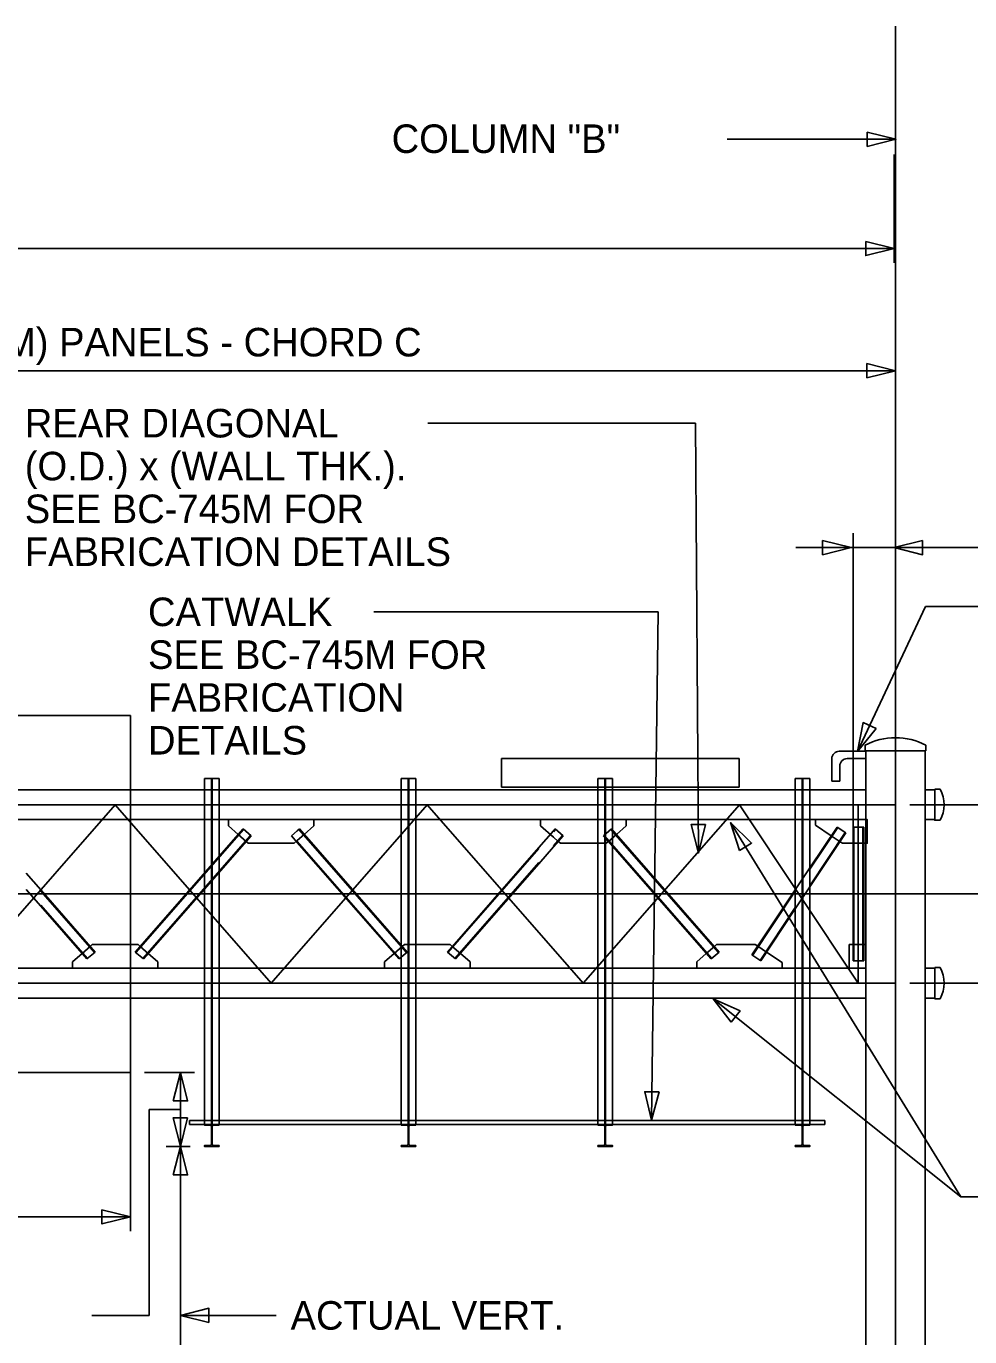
# Model space of a CAD drawing. Extents: x 3831399 to 3833095, y 499014 to 500202.
# Drawn here: x 3832657.9 to 3832754.1, y 499854.4 to 499988 of the extents above; entities that cross this region are included whole.
import ezdxf

# ---------------------------------------------------------------- set-up
doc = ezdxf.new("R2010")
doc.units = 0
for name, color, linetype in [('0-catwalk', 7, 'Continuous'), ('0-sign', 7, 'Continuous'), ('0-truss', 7, 'Continuous'), ('CenterLine', 7, 'Continuous'), ('Default', 7, 'Continuous'), ('DIM TXT', 7, 'Continuous'), ('structure', 7, 'Continuous')]:
    doc.layers.add(name, color=color, linetype=linetype)

msp = doc.modelspace()

# ---------------------------------------------------------------- linework, layer by layer
at = {"layer": '0-catwalk'}
for p, q in [((3832676.03, 499911.3), (3832677.52, 499911.3)), ((3832676.03, 499876.06), (3832676.03, 499911.3)), ((3832676.74, 499911.3), (3832676.81, 499911.3)), ((3832676.74, 499876.06), (3832676.74, 499911.3)), ((3832676.81, 499911.3), (3832676.81, 499876.06)), ((3832677.52, 499911.3), (3832677.52, 499876.06)), ((3832696.09, 499911.3), (3832697.58, 499911.3)), ((3832696.09, 499876.06), (3832696.09, 499911.3)), ((3832696.8, 499911.3), (3832696.87, 499911.3)), ((3832696.8, 499876.06), (3832696.8, 499911.3)), ((3832696.87, 499911.3), (3832696.87, 499876.06)), ((3832697.58, 499911.3), (3832697.58, 499876.06)), ((3832716.15, 499911.3), (3832717.64, 499911.3)), ((3832716.15, 499876.06), (3832716.15, 499911.3)), ((3832716.86, 499911.3), (3832716.93, 499911.3)), ((3832716.86, 499876.06), (3832716.86, 499911.3)), ((3832716.93, 499911.3), (3832716.93, 499876.06)), ((3832717.64, 499911.3), (3832717.64, 499876.06)), ((3832736.27, 499911.3), (3832737.76, 499911.3)), ((3832736.27, 499876.06), (3832736.27, 499911.3)), ((3832736.99, 499911.3), (3832737.05, 499911.3)), ((3832736.99, 499876.06), (3832736.99, 499911.3)), ((3832737.05, 499911.3), (3832737.05, 499876.06)), ((3832737.76, 499911.3), (3832737.76, 499876.06)), ((3832739.29, 499876.44), (3832674.5, 499876.44)), ((3832674.5, 499876.44), (3832674.5, 499876.06)), ((3832739.29, 499876.06), (3832739.29, 499876.44)), ((3832674.5, 499876.06), (3832739.29, 499876.06)), ((3832677.52, 499876.06), (3832676.03, 499876.06)), ((3832676.81, 499876.06), (3832676.74, 499876.06)), ((3832697.58, 499876.06), (3832696.09, 499876.06)), ((3832696.87, 499876.06), (3832696.8, 499876.06)), ((3832717.64, 499876.06), (3832716.15, 499876.06)), ((3832716.93, 499876.06), (3832716.86, 499876.06)), ((3832737.76, 499876.06), (3832736.27, 499876.06)), ((3832737.05, 499876.06), (3832736.99, 499876.06))]:
    msp.add_line(p, q, dxfattribs=at)
for points in [[(3832676.03, 499876.06), (3832677.52, 499876.06), (3832677.52, 499875.98), (3832676.94, 499875.98)], [(3832676.61, 499875.98), (3832676.03, 499875.98), (3832676.03, 499876.06)], [(3832676.74, 499874.04), (3832676.74, 499875.85)], [(3832676.81, 499875.85), (3832676.81, 499874.04)], [(3832696.09, 499876.06), (3832697.58, 499876.06), (3832697.58, 499875.98), (3832697, 499875.98)], [(3832696.67, 499875.98), (3832696.09, 499875.98), (3832696.09, 499876.06)], [(3832696.8, 499874.04), (3832696.8, 499875.85)], [(3832696.87, 499875.85), (3832696.87, 499874.04)], [(3832716.15, 499876.06), (3832717.64, 499876.06), (3832717.64, 499875.98), (3832717.06, 499875.98)], [(3832716.73, 499875.98), (3832716.15, 499875.98), (3832716.15, 499876.06)], [(3832716.86, 499874.04), (3832716.86, 499875.85)], [(3832716.93, 499875.85), (3832716.93, 499874.04)], [(3832736.27, 499876.06), (3832737.76, 499876.06), (3832737.76, 499875.98), (3832737.18, 499875.98)], [(3832736.85, 499875.98), (3832736.27, 499875.98), (3832736.27, 499876.06)], [(3832736.99, 499874.04), (3832736.99, 499875.85)], [(3832737.05, 499875.85), (3832737.05, 499874.04)], [(3832676.94, 499873.9), (3832677.52, 499873.9), (3832677.52, 499873.82), (3832676.03, 499873.82), (3832676.03, 499873.9), (3832676.61, 499873.9)], [(3832697, 499873.9), (3832697.58, 499873.9), (3832697.58, 499873.82), (3832696.09, 499873.82), (3832696.09, 499873.9), (3832696.67, 499873.9)], [(3832717.06, 499873.9), (3832717.64, 499873.9), (3832717.64, 499873.82), (3832716.15, 499873.82), (3832716.15, 499873.9), (3832716.73, 499873.9)], [(3832737.18, 499873.9), (3832737.76, 499873.9), (3832737.76, 499873.82), (3832736.27, 499873.82), (3832736.27, 499873.9), (3832736.85, 499873.9)]]:
    msp.add_lwpolyline(points, dxfattribs=at)
for centre, start, end in [((3832676.61, 499875.85), 360, 90), ((3832676.94, 499875.85), 90, 180), ((3832696.67, 499875.85), 360, 90), ((3832697, 499875.85), 90, 180), ((3832716.73, 499875.85), 360, 90), ((3832717.06, 499875.85), 90, 180), ((3832736.85, 499875.85), 360, 90), ((3832737.18, 499875.85), 90, 180), ((3832676.61, 499874.04), 270, 360), ((3832676.94, 499874.04), 180, 270), ((3832696.67, 499874.04), 270, 360), ((3832697, 499874.04), 180, 270), ((3832716.73, 499874.04), 270, 360), ((3832717.06, 499874.04), 180, 270), ((3832736.85, 499874.04), 270, 360), ((3832737.18, 499874.04), 180, 270)]:
    msp.add_arc(centre, 0.132, start, end, dxfattribs=at)
at = {"layer": '0-sign'}
for p, q in [((3832668.48, 499917.74), (3832554.81, 499917.74)), ((3832668.48, 499881.36), (3832668.48, 499917.74)), ((3832554.81, 499881.36), (3832668.48, 499881.36))]:
    msp.add_line(p, q, dxfattribs=at)
at = {"layer": '0-truss'}
for p, q in [((3832743.39, 499914.15), (3832743.39, 499914.72)), ((3832749.59, 499914.15), (3832743.39, 499914.15)), ((3832743.46, 499914.15), (3832743.46, 499801.79)), ((3832749.52, 499914.15), (3832749.52, 499801.79)), ((3832749.59, 499914.72), (3832749.59, 499914.15)), ((3832537.29, 499910.16), (3832685.48, 499910.16)), ((3832685.48, 499910.16), (3832711.62, 499910.16)), ((3832711.62, 499910.16), (3832737.76, 499910.16)), ((3832737.76, 499910.16), (3832743.46, 499910.16)), ((3832749.52, 499910.16), (3832750.49, 499910.16)), ((3832750.49, 499910.23), (3832751.05, 499910.23)), ((3832537.29, 499907.13), (3832685.48, 499907.13)), ((3832685.48, 499907.13), (3832710.13, 499907.13)), ((3832710.13, 499907.13), (3832711.62, 499907.13)), ((3832711.62, 499907.13), (3832710.31, 499907.13)), ((3832710.31, 499907.13), (3832710.31, 499906.48)), ((3832711.62, 499907.13), (3832737.76, 499907.13)), ((3832737.76, 499907.13), (3832743.46, 499907.13)), ((3832749.52, 499907.13), (3832750.49, 499907.13)), ((3832679.96, 499906.18), (3832668.98, 499893.63)), ((3832680.02, 499906.13), (3832669.04, 499893.58)), ((3832678.48, 499906.48), (3832679.46, 499905.62)), ((3832679.46, 499905.62), (3832680.28, 499904.9)), ((3832680.78, 499905.47), (3832679.96, 499906.18)), ((3832684.89, 499905.47), (3832685.48, 499905.98)), ((3832685.48, 499905.98), (3832685.71, 499906.18)), ((3832685.48, 499904.98), (3832686.21, 499905.62)), ((3832685.65, 499906.13), (3832696.63, 499893.58)), ((3832685.71, 499906.18), (3832696.69, 499893.63)), ((3832686.21, 499905.62), (3832687.19, 499906.48)), ((3832710.13, 499904.29), (3832711.62, 499905.99)), ((3832710.31, 499906.48), (3832711.62, 499905.33)), ((3832711.79, 499906.18), (3832711.62, 499905.99)), ((3832711.84, 499906.13), (3832711.62, 499905.88)), ((3832712.61, 499905.47), (3832711.79, 499906.18)), ((3832716.72, 499905.47), (3832717.54, 499906.18)), ((3832717.22, 499904.9), (3832718.04, 499905.62)), ((3832728.46, 499893.58), (3832717.48, 499906.13)), ((3832717.54, 499906.18), (3832728.52, 499893.63)), ((3832718.04, 499905.62), (3832719.02, 499906.48)), ((3832740.53, 499906.37), (3832737.76, 499902.22)), ((3832740.6, 499906.33), (3832737.76, 499902.08)), ((3832741.37, 499905.81), (3832737.76, 499900.39)), ((3832737.76, 499900.26), (3832741.44, 499905.77)), ((3832739.93, 499905.47), (3832738.32, 499906.55)), ((3832741.44, 499905.77), (3832740.53, 499906.37)), ((3832742.16, 499892.73), (3832742.16, 499906.37)), ((3832742.16, 499906.37), (3832743.25, 499906.37)), ((3832742.23, 499906.37), (3832742.23, 499892.73)), ((3832743.17, 499906.37), (3832743.17, 499892.73)), ((3832743.25, 499906.37), (3832743.25, 499892.73)), ((3832680.72, 499905.52), (3832669.74, 499892.97)), ((3832669.8, 499892.92), (3832680.78, 499905.47)), ((3832680.28, 499904.9), (3832680.5, 499904.71)), ((3832683.98, 499904.71), (3832685.17, 499904.71)), ((3832685.48, 499904.8), (3832684.89, 499905.47)), ((3832685.17, 499904.71), (3832685.48, 499904.98)), ((3832685.48, 499904.91), (3832695.93, 499892.97)), ((3832695.87, 499892.92), (3832685.48, 499904.8)), ((3832710.13, 499904.29), (3832700.81, 499893.63)), ((3832711.62, 499904.34), (3832710.13, 499902.63)), ((3832712.55, 499905.52), (3832711.62, 499904.46)), ((3832711.62, 499904.34), (3832712.61, 499905.47)), ((3832711.62, 499905.33), (3832712.11, 499904.9)), ((3832712.11, 499904.9), (3832712.32, 499904.71)), ((3832727.7, 499892.92), (3832716.72, 499905.47)), ((3832727.76, 499892.97), (3832716.78, 499905.52)), ((3832717, 499904.71), (3832717.22, 499904.9)), ((3832739.93, 499905.47), (3832740.84, 499904.87)), ((3832741.08, 499904.71), (3832740.84, 499904.87)), ((3832742.16, 499904.71), (3832743.25, 499904.71)), ((3832710.13, 499904.17), (3832700.86, 499893.58)), ((3832657.84, 499901.66), (3832659.33, 499899.96)), ((3832710.13, 499902.75), (3832701.57, 499892.97)), ((3832701.63, 499892.92), (3832710.13, 499902.63)), ((3832736.27, 499899.98), (3832737.76, 499902.22)), ((3832657.84, 499900.01), (3832659.33, 499898.3)), ((3832659.33, 499899.96), (3832664.87, 499893.63)), ((3832659.33, 499899.84), (3832664.81, 499893.58)), ((3832736.27, 499899.98), (3832731.84, 499893.33)), ((3832736.27, 499899.84), (3832731.9, 499893.29)), ((3832736.27, 499898.02), (3832737.76, 499900.26)), ((3832659.33, 499898.42), (3832664.1, 499892.97)), ((3832664.05, 499892.92), (3832659.33, 499898.3)), ((3832736.27, 499898.16), (3832732.68, 499892.77)), ((3832732.75, 499892.73), (3832736.27, 499898.02)), ((3832663.55, 499893.48), (3832664.37, 499894.2)), ((3832664.87, 499893.63), (3832664.05, 499892.92)), ((3832664.58, 499894.39), (3832664.37, 499894.2)), ((3832668.98, 499893.63), (3832669.8, 499892.92)), ((3832669.47, 499894.2), (3832669.26, 499894.39)), ((3832669.47, 499894.2), (3832670.29, 499893.48)), ((3832695.38, 499893.48), (3832696.2, 499894.2)), ((3832696.69, 499893.63), (3832695.87, 499892.92)), ((3832696.41, 499894.39), (3832696.2, 499894.2)), ((3832700.81, 499893.63), (3832701.63, 499892.92)), ((3832701.3, 499894.2), (3832701.09, 499894.39)), ((3832701.3, 499894.2), (3832702.12, 499893.48)), ((3832727.2, 499893.48), (3832728.02, 499894.2)), ((3832728.52, 499893.63), (3832727.7, 499892.92)), ((3832728.02, 499894.2), (3832728.24, 499894.39)), ((3832728.24, 499894.39), (3832732.2, 499894.39)), ((3832732.2, 499894.39), (3832732.44, 499894.23)), ((3832732.44, 499894.23), (3832733.34, 499893.63)), ((3832733.34, 499893.63), (3832734.93, 499892.57)), ((3832742.16, 499894.39), (3832741.78, 499894.39)), ((3832741.78, 499894.39), (3832741.78, 499891.97)), ((3832743.25, 499894.39), (3832742.16, 499894.39)), ((3832743.46, 499894.39), (3832743.25, 499894.39)), ((3832663.55, 499893.48), (3832662.56, 499892.62)), ((3832671.28, 499892.62), (3832670.29, 499893.48)), ((3832695.38, 499893.48), (3832694.39, 499892.62)), ((3832703.11, 499892.62), (3832702.12, 499893.48)), ((3832726.22, 499892.62), (3832727.2, 499893.48)), ((3832731.84, 499893.33), (3832732.75, 499892.73)), ((3832743.25, 499892.73), (3832742.16, 499892.73)), ((3832537.29, 499891.97), (3832685.48, 499891.97)), ((3832685.48, 499891.97), (3832711.62, 499891.97)), ((3832711.62, 499891.97), (3832737.76, 499891.97)), ((3832737.76, 499891.97), (3832743.46, 499891.97)), ((3832741.78, 499891.97), (3832743.46, 499891.97)), ((3832749.52, 499891.97), (3832750.49, 499891.97)), ((3832750.49, 499892.04), (3832751.05, 499892.04)), ((3832650.95, 499888.94), (3832685.48, 499888.94)), ((3832685.48, 499888.94), (3832711.62, 499888.94)), ((3832711.62, 499888.94), (3832736.27, 499888.94)), ((3832736.27, 499888.94), (3832743.46, 499888.94)), ((3832749.52, 499888.94), (3832750.49, 499888.94))]:
    msp.add_line(p, q, dxfattribs=at)
for points in [[(3832751.05, 499907.06), (3832750.49, 499907.06), (3832750.49, 499910.23)], [(3832683.98, 499907.13), (3832678.48, 499907.13), (3832678.48, 499906.48)], [(3832687.19, 499906.48), (3832687.19, 499907.13), (3832685.48, 499907.13)], [(3832719.02, 499906.48), (3832719.02, 499907.13), (3832711.62, 499907.13)], [(3832738.32, 499906.55), (3832738.32, 499907.13), (3832743.62, 499907.13), (3832743.62, 499904.71), (3832743.25, 499904.71)], [(3832680.5, 499904.71), (3832683.98, 499904.71)], [(3832712.32, 499904.71), (3832717, 499904.71)], [(3832742.16, 499904.71), (3832741.08, 499904.71)], [(3832669.26, 499894.39), (3832664.58, 499894.39)], [(3832701.09, 499894.39), (3832696.41, 499894.39)], [(3832662.56, 499892.62), (3832662.56, 499891.97), (3832671.28, 499891.97), (3832671.28, 499892.62)], [(3832694.39, 499892.62), (3832694.39, 499891.97), (3832703.11, 499891.97), (3832703.11, 499892.62)], [(3832734.93, 499892.57), (3832734.93, 499891.97), (3832726.22, 499891.97), (3832726.22, 499892.62)], [(3832751.05, 499888.87), (3832750.49, 499888.87), (3832750.49, 499892.04)]]:
    msp.add_lwpolyline(points, dxfattribs=at)
for centre, radius, start, end in [((3832746.49, 499908.65), 6.82, 62.944, 117.056), ((3832747.95, 499908.64), 3.49, 332.944, 27.056), ((3832747.95, 499890.46), 3.49, 332.944, 27.056)]:
    msp.add_arc(centre, radius, start, end, dxfattribs=at)
at = {"layer": 'CenterLine'}
for p, q in [((3832746.49, 499988), (3832746.49, 499778.49)), ((3832332.74, 499908.64), (3832746.49, 499908.64)), ((3832666.92, 499908.64), (3832651.01, 499890.46)), ((3832666.92, 499908.64), (3832682.84, 499890.46)), ((3832698.75, 499908.64), (3832682.84, 499890.46)), ((3832698.75, 499908.64), (3832714.66, 499890.46)), ((3832730.58, 499908.64), (3832714.66, 499890.46)), ((3832730.58, 499908.64), (3832742.7, 499890.46)), ((3832742.7, 499890.46), (3832742.7, 499908.64)), ((3832308.87, 499899.55), (3832771.9, 499899.55)), ((3832332.74, 499890.46), (3832746.49, 499890.46))]:
    msp.add_line(p, q, dxfattribs=at)
at = {"layer": 'Default'}
for p, q in [((3832706.31, 499913.34), (3832730.56, 499913.34)), ((3832706.31, 499910.43), (3832706.31, 499913.34)), ((3832730.56, 499913.34), (3832730.56, 499910.43)), ((3832730.56, 499910.43), (3832706.31, 499910.43))]:
    msp.add_line(p, q, dxfattribs=at)
at = {"layer": 'DIM TXT'}
for p, q in [((3832729.33, 499976.48), (3832735.15, 499976.48)), ((3832746.53, 499976.48), (3832735.15, 499976.48)), ((3832746.37, 499974.94), (3832746.37, 499963.89)), ((3832332.74, 499965.35), (3832746.37, 499965.35)), ((3832746.49, 499938.95), (3832746.49, 499954.34)), ((3832619.18, 499952.88), (3832746.49, 499952.88)), ((3832720.27, 499947.53), (3832698.8, 499947.53)), ((3832720.27, 499947.53), (3832726.09, 499947.53)), ((3832726.42, 499903.72), (3832726.09, 499947.53)), ((3832742.16, 499906.37), (3832742.16, 499936.32)), ((3832746.49, 499916.92), (3832746.49, 499936.32)), ((3832736.34, 499934.87), (3832742.16, 499934.87)), ((3832742.16, 499934.87), (3832746.49, 499934.87)), ((3832790.78, 499934.87), (3832746.49, 499934.87)), ((3832742.62, 499914.08), (3832749.55, 499928.85)), ((3832755.37, 499928.85), (3832749.55, 499928.85)), ((3832716.47, 499928.31), (3832693.31, 499928.31)), ((3832716.47, 499928.31), (3832722.29, 499928.31)), ((3832721.62, 499876.48), (3832722.29, 499928.31)), ((3832747.95, 499908.64), (3832758.3, 499908.64)), ((3832729.68, 499906.83), (3832753.15, 499868.69)), ((3832747.95, 499890.46), (3832758.3, 499890.46)), ((3832727.91, 499888.87), (3832753.15, 499868.69)), ((3832668.48, 499881.36), (3832668.48, 499865.18)), ((3832669.93, 499881.36), (3832675.03, 499881.36)), ((3832673.57, 499873.82), (3832673.57, 499881.36)), ((3832673.57, 499877.59), (3832670.38, 499877.59)), ((3832670.38, 499877.59), (3832670.38, 499856.59)), ((3832674.57, 499873.82), (3832672.12, 499873.82)), ((3832674.57, 499873.82), (3832672.12, 499873.82)), ((3832673.57, 499839.36), (3832673.57, 499873.82)), ((3832758.97, 499868.69), (3832753.15, 499868.69)), ((3832758.97, 499868.69), (3832753.15, 499868.69)), ((3832554.81, 499866.64), (3832668.48, 499866.64)), ((3832664.56, 499856.59), (3832670.38, 499856.59)), ((3832673.57, 499856.59), (3832677.53, 499856.59)), ((3832683.35, 499856.59), (3832677.53, 499856.59))]:
    msp.add_line(p, q, dxfattribs=at)
for points in [[(3832743.62, 499977.21), (3832746.53, 499976.48), (3832743.62, 499975.75)], [(3832743.46, 499966.07), (3832746.37, 499965.35), (3832743.46, 499964.62)], [(3832743.58, 499953.61), (3832746.49, 499952.88), (3832743.58, 499952.16)], [(3832739.06, 499935.59), (3832741.97, 499934.86), (3832739.06, 499934.13)], [(3832749.25, 499935.59), (3832746.34, 499934.86), (3832749.25, 499934.13)], [(3832744.51, 499916.4), (3832742.62, 499914.08), (3832743.19, 499917.02)], [(3832727.12, 499906.64), (3832726.42, 499903.72), (3832725.67, 499906.63)], [(3832730.59, 499903.97), (3832729.68, 499906.83), (3832731.82, 499904.73)], [(3832729.73, 499886.48), (3832727.91, 499888.87), (3832730.64, 499887.62)], [(3832672.84, 499878.45), (3832673.57, 499881.36), (3832674.3, 499878.45)], [(3832722.38, 499879.38), (3832721.62, 499876.48), (3832720.93, 499879.39)], [(3832674.3, 499876.73), (3832673.57, 499873.82), (3832672.84, 499876.73)], [(3832672.84, 499870.91), (3832673.57, 499873.82), (3832674.3, 499870.91)], [(3832665.57, 499867.36), (3832668.48, 499866.64), (3832665.57, 499865.91)], [(3832676.48, 499855.86), (3832673.57, 499856.59), (3832676.48, 499857.32)]]:
    msp.add_lwpolyline(points, close=True, dxfattribs=at)
at = {"layer": 'structure'}
for p, q in [((3832743.45, 499914.09), (3832740.75, 499914.09)), ((3832740, 499913.34), (3832740, 499911.03)), ((3832740.82, 499912.58), (3832740.82, 499911.03)), ((3832743.45, 499913.34), (3832741.55, 499913.34)), ((3832740.82, 499911.03), (3832740, 499911.03))]:
    msp.add_line(p, q, dxfattribs=at)
for centre in [(3832740.76, 499913.34), (3832741.57, 499912.58)]:
    msp.add_arc(centre, 0.758, 90, 180, dxfattribs=at)

# ---------------------------------------------------------------- texts
at = {"layer": 'DIM TXT'}
for s, height, p in [('  COLUMN "B"', 2.9099, (3832692.95, 499975.08)), ('(M) PANELS - CHORD C', 2.9099, (3832654.29, 499954.34)), ('REAR DIAGONAL', 2.9099, (3832657.71, 499946.08)), ('(O.D.) x (WALL THK.).', 2.9099, (3832657.71, 499941.71)), ('SEE BC-745M FOR', 2.9099, (3832657.71, 499937.35)), ('FABRICATION DETAILS', 2.9099, (3832657.71, 499932.98)), ('CATWALK', 2.91, (3832670.27, 499926.85)), ('SEE BC-745M FOR', 2.9099, (3832670.27, 499922.49)), ('FABRICATION', 2.9099, (3832670.27, 499918.12)), ('DETAILS', 2.91, (3832670.27, 499913.76)), ('ACTUAL VERT.', 2.9099, (3832684.81, 499855.13))]:
    msp.add_text(s, height=height, dxfattribs=at).set_placement(p)

doc.saveas('drawing.dxf')
